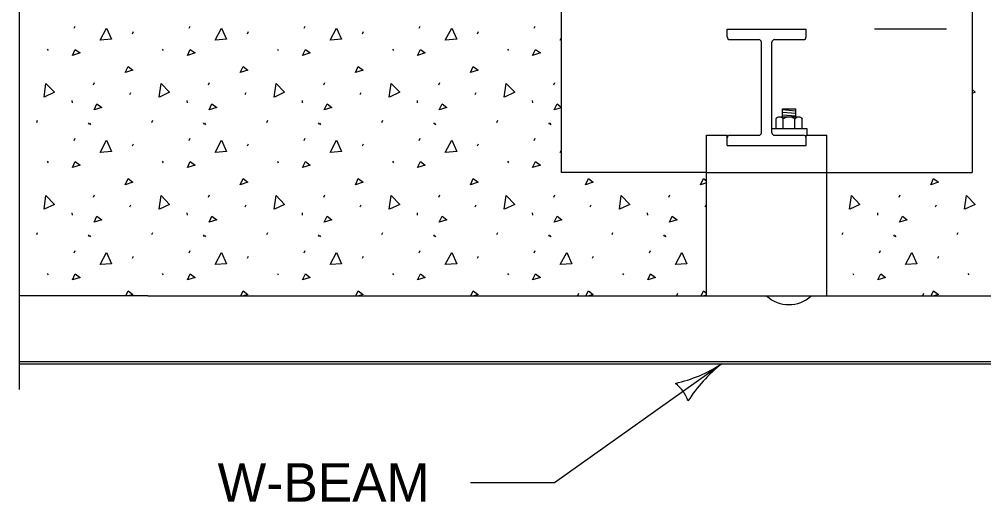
# Model space of a CAD drawing. Extents: x 49991.4 to 50021, y 49987.6 to 50011.4.
# Drawn here: x 50005.327 to 50006.829, y 49990.485 to 49991.236 of the extents above; entities that cross this region are included whole.
import ezdxf

# ---------------------------------------------------------------- set-up
doc = ezdxf.new("R2010")
doc.units = 0
for name, color, linetype in [('Level 1', 7, 'Continuous'), ('Level 2', 7, 'Continuous'), ('Level 3', 7, 'Continuous'), ('Level 4', 7, 'Continuous'), ('Level 6', 7, 'Continuous')]:
    doc.layers.add(name, color=color, linetype=linetype)

msp = doc.modelspace()

# ---------------------------------------------------------------- linework, layer by layer
at = {"layer": 'Level 1'}
for p, q in [((50006.1711, 49991.3177), (50006.1711, 49990.9977)), ((50006.8111, 49991.3177), (50006.8111, 49990.9977)), ((50005.4125, 49991.2224), (50005.414, 49991.2257)), ((50005.5917, 49991.2224), (50005.5932, 49991.2257)), ((50005.7708, 49991.2224), (50005.7723, 49991.2257)), ((50005.95, 49991.2224), (50005.9515, 49991.2257)), ((50006.1291, 49991.2224), (50006.1306, 49991.2257)), ((50005.5033, 49991.2138), (50005.5048, 49991.2171)), ((50005.6824, 49991.2138), (50005.6839, 49991.2171)), ((50005.8616, 49991.2138), (50005.8631, 49991.2171)), ((50006.0407, 49991.2138), (50006.0422, 49991.2171)), ((50006.4294, 49991.2209), (50006.5524, 49991.2209)), ((50006.4294, 49991.2088), (50006.4294, 49991.2209)), ((50006.5524, 49991.2088), (50006.5524, 49991.2209)), ((50006.1696, 49991.2037), (50006.1711, 49991.2067)), ((50006.1711, 49991.2038), (50006.1699, 49991.2037)), ((50006.4335, 49991.2047), (50006.4786, 49991.2047)), ((50006.4827, 49991.0598), (50006.4827, 49991.2007)), ((50006.4991, 49991.0598), (50006.4991, 49991.2007)), ((50006.5032, 49991.2047), (50006.5483, 49991.2047)), ((50005.3707, 49991.1899), (50005.3722, 49991.1877)), ((50005.4099, 49991.1802), (50005.4144, 49991.1895)), ((50005.4218, 49991.184), (50005.4099, 49991.1802)), ((50005.4144, 49991.1895), (50005.4218, 49991.184)), ((50005.5499, 49991.1899), (50005.5514, 49991.1877)), ((50005.5891, 49991.1802), (50005.5935, 49991.1895)), ((50005.601, 49991.184), (50005.5891, 49991.1802)), ((50005.5935, 49991.1895), (50005.601, 49991.184)), ((50005.7291, 49991.1899), (50005.7305, 49991.1877)), ((50005.7682, 49991.1802), (50005.7727, 49991.1895)), ((50005.7801, 49991.184), (50005.7682, 49991.1802)), ((50005.7727, 49991.1895), (50005.7801, 49991.184)), ((50005.9082, 49991.1899), (50005.9097, 49991.1877)), ((50005.9474, 49991.1802), (50005.9518, 49991.1895)), ((50005.9593, 49991.184), (50005.9474, 49991.1802)), ((50005.9518, 49991.1895), (50005.9593, 49991.184)), ((50006.0874, 49991.1899), (50006.0889, 49991.1877)), ((50006.1265, 49991.1802), (50006.131, 49991.1895)), ((50006.1385, 49991.184), (50006.1265, 49991.1802)), ((50006.131, 49991.1895), (50006.1385, 49991.184)), ((50005.4429, 49991.1343), (50005.4443, 49991.1377)), ((50005.622, 49991.1343), (50005.6235, 49991.1377)), ((50005.8012, 49991.1343), (50005.8027, 49991.1377)), ((50005.9803, 49991.1343), (50005.9818, 49991.1377)), ((50006.1595, 49991.1343), (50006.161, 49991.1377)), ((50005.4995, 49991.1191), (50005.501, 49991.1224)), ((50005.6787, 49991.1191), (50005.6802, 49991.1224)), ((50005.8579, 49991.1191), (50005.8594, 49991.1224)), ((50006.037, 49991.1191), (50006.0385, 49991.1224)), ((50005.4091, 49991.1097), (50005.4094, 49991.1063)), ((50005.5882, 49991.1097), (50005.5886, 49991.1063)), ((50005.7674, 49991.1097), (50005.7677, 49991.1063)), ((50005.9465, 49991.1097), (50005.9469, 49991.1063)), ((50006.1257, 49991.1097), (50006.1261, 49991.1063)), ((50006.1711, 49991.0986), (50006.1602, 49991.0952)), ((50006.5154, 49991.0969), (50006.5364, 49991.0969)), ((50006.5154, 49991.084), (50006.5154, 49991.0969)), ((50006.5154, 49991.0957), (50006.5364, 49991.0939)), ((50006.5154, 49991.0918), (50006.5364, 49991.0902)), ((50006.5364, 49991.0841), (50006.5364, 49991.0969)), ((50005.3543, 49991.0758), (50005.3558, 49991.0792)), ((50005.4345, 49991.0753), (50005.436, 49991.0731)), ((50005.4365, 49991.0744), (50005.438, 49991.0722)), ((50005.5335, 49991.0758), (50005.535, 49991.0792)), ((50005.6137, 49991.0753), (50005.6152, 49991.0731)), ((50005.6157, 49991.0744), (50005.6172, 49991.0722)), ((50005.7126, 49991.0758), (50005.7141, 49991.0792)), ((50005.7928, 49991.0753), (50005.7943, 49991.0731)), ((50005.7948, 49991.0744), (50005.7963, 49991.0722)), ((50005.8918, 49991.0758), (50005.8933, 49991.0792)), ((50005.972, 49991.0753), (50005.9735, 49991.0731)), ((50005.974, 49991.0744), (50005.9755, 49991.0722)), ((50006.071, 49991.0758), (50006.0724, 49991.0792)), ((50006.1511, 49991.0753), (50006.1526, 49991.0731)), ((50006.1531, 49991.0744), (50006.1546, 49991.0722)), ((50006.5052, 49991.0812), (50006.5052, 49991.0661)), ((50006.5407, 49991.0841), (50006.511, 49991.084)), ((50006.5154, 49991.0878), (50006.5364, 49991.0861)), ((50006.5166, 49991.0661), (50006.5166, 49991.0812)), ((50006.535, 49991.0661), (50006.535, 49991.0811)), ((50006.5464, 49991.0661), (50006.5464, 49991.0812)), ((50006.4991, 49991.0661), (50006.5536, 49991.0661)), ((50006.5536, 49991.0661), (50006.5536, 49991.0558)), ((50005.4125, 49991.0476), (50005.414, 49991.051)), ((50005.5917, 49991.0476), (50005.5932, 49991.051)), ((50005.7708, 49991.0476), (50005.7723, 49991.051)), ((50005.95, 49991.0476), (50005.9515, 49991.051)), ((50006.1291, 49991.0476), (50006.1306, 49991.051)), ((50006.397, 49991.0558), (50006.4294, 49991.0558)), ((50006.397, 49990.8057), (50006.397, 49991.0558)), ((50006.4294, 49991.0397), (50006.4294, 49991.0558)), ((50006.4335, 49991.0558), (50006.4786, 49991.0558)), ((50006.5032, 49991.0558), (50006.5483, 49991.0558)), ((50006.5524, 49991.0397), (50006.5524, 49991.0558)), ((50006.5524, 49991.0558), (50006.5846, 49991.0558)), ((50006.5846, 49990.8057), (50006.5846, 49991.0558)), ((50005.5033, 49991.0391), (50005.5048, 49991.0424)), ((50005.6824, 49991.0391), (50005.6839, 49991.0424)), ((50005.8616, 49991.0391), (50005.8631, 49991.0424)), ((50006.0407, 49991.0391), (50006.0422, 49991.0424)), ((50006.1696, 49991.029), (50006.1711, 49991.0319)), ((50006.1711, 49991.0291), (50006.1699, 49991.029)), ((50006.4294, 49991.0397), (50006.5524, 49991.0397)), ((50005.3707, 49991.0152), (50005.3722, 49991.013)), ((50005.4099, 49991.0055), (50005.4144, 49991.0148)), ((50005.4144, 49991.0148), (50005.4218, 49991.0092)), ((50005.5499, 49991.0152), (50005.5514, 49991.013)), ((50005.5891, 49991.0055), (50005.5935, 49991.0148)), ((50005.5935, 49991.0148), (50005.601, 49991.0092)), ((50005.7291, 49991.0152), (50005.7305, 49991.013)), ((50005.7682, 49991.0055), (50005.7727, 49991.0148)), ((50005.7727, 49991.0148), (50005.7801, 49991.0092)), ((50005.9082, 49991.0152), (50005.9097, 49991.013)), ((50005.9474, 49991.0055), (50005.9518, 49991.0148)), ((50005.9518, 49991.0148), (50005.9593, 49991.0092)), ((50006.0874, 49991.0152), (50006.0889, 49991.013)), ((50006.1265, 49991.0055), (50006.131, 49991.0148)), ((50006.131, 49991.0148), (50006.1385, 49991.0092)), ((50005.4218, 49991.0092), (50005.4099, 49991.0055)), ((50005.601, 49991.0092), (50005.5891, 49991.0055)), ((50005.7801, 49991.0092), (50005.7682, 49991.0055)), ((50005.9593, 49991.0092), (50005.9474, 49991.0055)), ((50006.1385, 49991.0092), (50006.1265, 49991.0055)), ((50006.3971, 49990.9977), (50006.1711, 49990.9977)), ((50006.5846, 49990.9977), (50006.8111, 49990.9977)), ((50006.3971, 49990.9817), (50006.3879, 49990.9788)), ((50005.4429, 49990.9596), (50005.4443, 49990.963)), ((50005.622, 49990.9596), (50005.6235, 49990.963)), ((50005.8012, 49990.9596), (50005.8027, 49990.963)), ((50005.9803, 49990.9596), (50005.9818, 49990.963)), ((50006.1595, 49990.9596), (50006.161, 49990.963)), ((50006.3386, 49990.9596), (50006.3401, 49990.963)), ((50006.697, 49990.9596), (50006.6985, 49990.963)), ((50005.4995, 49990.9443), (50005.501, 49990.9477)), ((50005.6787, 49990.9443), (50005.6802, 49990.9477)), ((50005.8579, 49990.9443), (50005.8594, 49990.9477)), ((50006.037, 49990.9443), (50006.0385, 49990.9477)), ((50006.2162, 49990.9443), (50006.2177, 49990.9477)), ((50006.3953, 49990.9443), (50006.3968, 49990.9477)), ((50006.7537, 49990.9443), (50006.7551, 49990.9477)), ((50005.4091, 49990.935), (50005.4094, 49990.9316)), ((50005.5882, 49990.935), (50005.5886, 49990.9316)), ((50005.7674, 49990.935), (50005.7677, 49990.9316)), ((50005.9465, 49990.935), (50005.9469, 49990.9316)), ((50006.1257, 49990.935), (50006.1261, 49990.9316)), ((50006.3048, 49990.935), (50006.3052, 49990.9316)), ((50006.6632, 49990.935), (50006.6635, 49990.9316)), ((50005.3543, 49990.9011), (50005.3558, 49990.9044)), ((50005.4345, 49990.9006), (50005.436, 49990.8983)), ((50005.4365, 49990.8997), (50005.438, 49990.8975)), ((50005.5335, 49990.9011), (50005.535, 49990.9044)), ((50005.6137, 49990.9006), (50005.6152, 49990.8983)), ((50005.6157, 49990.8997), (50005.6172, 49990.8975)), ((50005.7126, 49990.9011), (50005.7141, 49990.9044)), ((50005.7928, 49990.9006), (50005.7943, 49990.8983)), ((50005.7948, 49990.8997), (50005.7963, 49990.8975)), ((50005.8918, 49990.9011), (50005.8933, 49990.9044)), ((50005.972, 49990.9006), (50005.9735, 49990.8983)), ((50005.974, 49990.8997), (50005.9755, 49990.8975)), ((50006.071, 49990.9011), (50006.0724, 49990.9044)), ((50006.1511, 49990.9006), (50006.1526, 49990.8983)), ((50006.1531, 49990.8997), (50006.1546, 49990.8975)), ((50006.2501, 49990.9011), (50006.2516, 49990.9044)), ((50006.3303, 49990.9006), (50006.3318, 49990.8983)), ((50006.3323, 49990.8997), (50006.3338, 49990.8975)), ((50006.6084, 49990.9011), (50006.6099, 49990.9044)), ((50006.6886, 49990.9006), (50006.6901, 49990.8983)), ((50006.6906, 49990.8997), (50006.6921, 49990.8975)), ((50006.7876, 49990.9011), (50006.7891, 49990.9044)), ((50005.4125, 49990.8729), (50005.414, 49990.8763)), ((50005.5033, 49990.8643), (50005.5048, 49990.8677)), ((50005.5917, 49990.8729), (50005.5932, 49990.8763)), ((50005.6824, 49990.8643), (50005.6839, 49990.8677)), ((50005.7708, 49990.8729), (50005.7723, 49990.8763)), ((50005.8616, 49990.8643), (50005.8631, 49990.8677)), ((50005.95, 49990.8729), (50005.9515, 49990.8763)), ((50006.0407, 49990.8643), (50006.0422, 49990.8677)), ((50006.1291, 49990.8729), (50006.1306, 49990.8763)), ((50006.2199, 49990.8643), (50006.2214, 49990.8677)), ((50006.3083, 49990.8729), (50006.3098, 49990.8763)), ((50006.6666, 49990.8729), (50006.6681, 49990.8763)), ((50006.7574, 49990.8643), (50006.7589, 49990.8677)), ((50005.3707, 49990.8405), (50005.3722, 49990.8382)), ((50005.4099, 49990.8308), (50005.4144, 49990.8401)), ((50005.4218, 49990.8345), (50005.4099, 49990.8308)), ((50005.4144, 49990.8401), (50005.4218, 49990.8345)), ((50005.5499, 49990.8405), (50005.5514, 49990.8382)), ((50005.5891, 49990.8308), (50005.5935, 49990.8401)), ((50005.601, 49990.8345), (50005.5891, 49990.8308)), ((50005.5935, 49990.8401), (50005.601, 49990.8345)), ((50005.7291, 49990.8405), (50005.7305, 49990.8382)), ((50005.7682, 49990.8308), (50005.7727, 49990.8401)), ((50005.7801, 49990.8345), (50005.7682, 49990.8308)), ((50005.7727, 49990.8401), (50005.7801, 49990.8345)), ((50005.9082, 49990.8405), (50005.9097, 49990.8382)), ((50005.9474, 49990.8308), (50005.9518, 49990.8401)), ((50005.9593, 49990.8345), (50005.9474, 49990.8308)), ((50005.9518, 49990.8401), (50005.9593, 49990.8345)), ((50006.0874, 49990.8405), (50006.0889, 49990.8382)), ((50006.1265, 49990.8308), (50006.131, 49990.8401)), ((50006.1385, 49990.8345), (50006.1265, 49990.8308)), ((50006.131, 49990.8401), (50006.1385, 49990.8345)), ((50006.2665, 49990.8405), (50006.268, 49990.8382)), ((50006.3057, 49990.8308), (50006.3102, 49990.8401)), ((50006.3176, 49990.8345), (50006.3057, 49990.8308)), ((50006.3102, 49990.8401), (50006.3176, 49990.8345)), ((50006.6248, 49990.8405), (50006.6263, 49990.8382)), ((50006.664, 49990.8308), (50006.6685, 49990.8401)), ((50006.6759, 49990.8345), (50006.664, 49990.8308)), ((50006.6685, 49990.8401), (50006.6759, 49990.8345)), ((50006.804, 49990.8405), (50006.8055, 49990.8382)), ((50005.5272, 49990.8057), (50005.3272, 49990.8057)), ((50005.5272, 49990.8057), (50007.455, 49990.8057)), ((50006.1968, 49990.8063), (50006.1983, 49990.8097)), ((50006.3509, 49990.8063), (50006.3524, 49990.8097)), ((50006.3971, 49990.807), (50006.393, 49990.8057)), ((50006.7343, 49990.8063), (50006.7358, 49990.8097)), ((50005.3272, 49990.7036), (50007.655, 49990.7036)), ((50005.3272, 49990.6997), (50007.655, 49990.6997))]:
    msp.add_line(p, q, dxfattribs=at)
for points in [[(50005.4529, 49991.2037), (50005.463, 49991.2227), (50005.4708, 49991.2052), (50005.4533, 49991.2037)], [(50005.6321, 49991.2037), (50005.6421, 49991.2227), (50005.65, 49991.2052), (50005.6325, 49991.2037)], [(50005.8112, 49991.2037), (50005.8213, 49991.2227), (50005.8291, 49991.2052), (50005.8116, 49991.2037)], [(50005.9904, 49991.2037), (50006.0005, 49991.2227), (50006.0083, 49991.2052), (50005.9908, 49991.2037)], [(50005.4922, 49991.1536), (50005.4966, 49991.1629), (50005.5041, 49991.1573), (50005.4922, 49991.1536)], [(50005.6713, 49991.1536), (50005.6758, 49991.1629), (50005.6833, 49991.1573), (50005.6713, 49991.1536)], [(50005.8505, 49991.1536), (50005.8549, 49991.1629), (50005.8624, 49991.1573), (50005.8505, 49991.1536)], [(50006.0296, 49991.1536), (50006.0341, 49991.1629), (50006.0416, 49991.1573), (50006.0296, 49991.1536)], [(50005.3658, 49991.1152), (50005.3687, 49991.1365), (50005.3821, 49991.1227), (50005.3661, 49991.1153)], [(50005.5449, 49991.1152), (50005.5479, 49991.1365), (50005.5612, 49991.1227), (50005.5453, 49991.1153)], [(50005.7241, 49991.1152), (50005.727, 49991.1365), (50005.7404, 49991.1227), (50005.7244, 49991.1153)], [(50005.9032, 49991.1152), (50005.9062, 49991.1365), (50005.9195, 49991.1227), (50005.9036, 49991.1153)], [(50006.0824, 49991.1152), (50006.0853, 49991.1365), (50006.0987, 49991.1227), (50006.0827, 49991.1153)], [(50006.8111, 49991.1271), (50006.8153, 49991.1227), (50006.8111, 49991.1208)], [(50005.4436, 49991.0952), (50005.4481, 49991.1045), (50005.4555, 49991.0989), (50005.4436, 49991.0952)], [(50005.6228, 49991.0952), (50005.6272, 49991.1045), (50005.6347, 49991.0989), (50005.6228, 49991.0952)], [(50005.8019, 49991.0952), (50005.8064, 49991.1045), (50005.8138, 49991.0989), (50005.8019, 49991.0952)], [(50005.9811, 49991.0952), (50005.9855, 49991.1045), (50005.993, 49991.0989), (50005.9811, 49991.0952)], [(50006.1602, 49991.0952), (50006.1647, 49991.1045), (50006.1711, 49991.0997)], [(50005.4529, 49991.029), (50005.463, 49991.048), (50005.4708, 49991.0305), (50005.4533, 49991.029)], [(50005.6321, 49991.029), (50005.6421, 49991.048), (50005.65, 49991.0305), (50005.6325, 49991.029)], [(50005.8112, 49991.029), (50005.8213, 49991.048), (50005.8291, 49991.0305), (50005.8116, 49991.029)], [(50005.9904, 49991.029), (50006.0005, 49991.048), (50006.0083, 49991.0305), (50005.9908, 49991.029)], [(50005.4922, 49990.9788), (50005.4966, 49990.9882), (50005.5041, 49990.9826), (50005.4922, 49990.9788)], [(50005.6713, 49990.9788), (50005.6758, 49990.9882), (50005.6833, 49990.9826), (50005.6713, 49990.9788)], [(50005.8505, 49990.9788), (50005.8549, 49990.9882), (50005.8624, 49990.9826), (50005.8505, 49990.9788)], [(50006.0296, 49990.9788), (50006.0341, 49990.9882), (50006.0416, 49990.9826), (50006.0296, 49990.9788)], [(50006.2088, 49990.9788), (50006.2133, 49990.9882), (50006.2207, 49990.9826), (50006.2088, 49990.9788)], [(50006.3879, 49990.9788), (50006.3924, 49990.9882), (50006.3971, 49990.9847)], [(50006.7463, 49990.9788), (50006.7507, 49990.9882), (50006.7582, 49990.9826), (50006.7463, 49990.9788)], [(50005.3658, 49990.9405), (50005.3687, 49990.9618), (50005.3821, 49990.948), (50005.3661, 49990.9406)], [(50005.5449, 49990.9405), (50005.5479, 49990.9618), (50005.5612, 49990.948), (50005.5453, 49990.9406)], [(50005.7241, 49990.9405), (50005.727, 49990.9618), (50005.7404, 49990.948), (50005.7244, 49990.9406)], [(50005.9032, 49990.9405), (50005.9062, 49990.9618), (50005.9195, 49990.948), (50005.9036, 49990.9406)], [(50006.0824, 49990.9405), (50006.0853, 49990.9618), (50006.0987, 49990.948), (50006.0827, 49990.9406)], [(50006.2616, 49990.9405), (50006.2645, 49990.9618), (50006.2779, 49990.948), (50006.2619, 49990.9406)], [(50006.6199, 49990.9405), (50006.6228, 49990.9618), (50006.6362, 49990.948), (50006.6202, 49990.9406)], [(50006.799, 49990.9405), (50006.802, 49990.9618), (50006.8153, 49990.948), (50006.7994, 49990.9406)], [(50005.4436, 49990.9205), (50005.4481, 49990.9298), (50005.4555, 49990.9242), (50005.4436, 49990.9205)], [(50005.6228, 49990.9205), (50005.6272, 49990.9298), (50005.6347, 49990.9242), (50005.6228, 49990.9205)], [(50005.8019, 49990.9205), (50005.8064, 49990.9298), (50005.8138, 49990.9242), (50005.8019, 49990.9205)], [(50005.9811, 49990.9205), (50005.9855, 49990.9298), (50005.993, 49990.9242), (50005.9811, 49990.9205)], [(50006.1602, 49990.9205), (50006.1647, 49990.9298), (50006.1722, 49990.9242), (50006.1602, 49990.9205)], [(50006.3394, 49990.9205), (50006.3439, 49990.9298), (50006.3513, 49990.9242), (50006.3394, 49990.9205)], [(50006.6977, 49990.9205), (50006.7022, 49990.9298), (50006.7096, 49990.9242), (50006.6977, 49990.9205)], [(50005.4529, 49990.8543), (50005.463, 49990.8733), (50005.4708, 49990.8558), (50005.4533, 49990.8543)], [(50005.6321, 49990.8543), (50005.6421, 49990.8733), (50005.65, 49990.8558), (50005.6325, 49990.8543)], [(50005.8112, 49990.8543), (50005.8213, 49990.8733), (50005.8291, 49990.8558), (50005.8116, 49990.8543)], [(50005.9904, 49990.8543), (50006.0005, 49990.8733), (50006.0083, 49990.8558), (50005.9908, 49990.8543)], [(50006.1696, 49990.8543), (50006.1796, 49990.8733), (50006.1875, 49990.8558), (50006.1699, 49990.8543)], [(50006.3487, 49990.8543), (50006.3588, 49990.8733), (50006.3666, 49990.8558), (50006.3491, 49990.8543)], [(50006.707, 49990.8543), (50006.7171, 49990.8733), (50006.7249, 49990.8558), (50006.7074, 49990.8543)], [(50005.4929, 49990.8057), (50005.4966, 49990.8134), (50005.5041, 49990.8079), (50005.4972, 49990.8057)], [(50005.6721, 49990.8057), (50005.6758, 49990.8134), (50005.6833, 49990.8079), (50005.6763, 49990.8057)], [(50005.8512, 49990.8057), (50005.8549, 49990.8134), (50005.8624, 49990.8079), (50005.8555, 49990.8057)], [(50006.0304, 49990.8057), (50006.0341, 49990.8134), (50006.0416, 49990.8079), (50006.0347, 49990.8057)], [(50006.2095, 49990.8057), (50006.2133, 49990.8134), (50006.2207, 49990.8079), (50006.2138, 49990.8057)], [(50006.3887, 49990.8057), (50006.3924, 49990.8134), (50006.3971, 49990.81)], [(50006.747, 49990.8057), (50006.7507, 49990.8134), (50006.7582, 49990.8079), (50006.7513, 49990.8057)]]:
    msp.add_lwpolyline(points, dxfattribs=at)
for centre, major_axis, start_param, end_param in [((50006.4335, 49991.2088), (0.0041, 0), 3.141593, 4.712389), ((50006.5483, 49991.2088), (0.0041, 0), 4.712389, 6.283185), ((50006.4786, 49991.2007), (0.0041, 0), 0, 1.570796), ((50006.5032, 49991.2007), (-0.0041, 0), 4.712389, 6.283185), ((50006.5109, 49991.077), (0.00714, 0), 0.651429, 2.497647), ((50006.5257, 49991.0686), (-0.0158, 0), 4.078615, 5.329167), ((50006.5408, 49991.0773), (-0.00692, 0), 3.760637, 5.689405), ((50006.4786, 49991.0598), (0.0041, 0), 4.712389, 6.283185), ((50006.5032, 49991.0598), (0.0041, 0), 3.141593, 4.712389), ((50006.4335, 49991.0518), (-0.0041, 0), 4.712389, 6.234181), ((50006.5483, 49991.0518), (-0.0041, 0), 3.190597, 4.712389)]:
    msp.add_ellipse(centre, major_axis=major_axis, ratio=0.983731, start_param=start_param, end_param=end_param, dxfattribs=at)
at = {"layer": 'Level 3'}
for p, q in [((50006.7711, 49991.2209), (50006.659, 49991.2209)), ((50006.1603, 49990.5152), (50006.4207, 49990.6997)), ((50006.0298, 49990.5152), (50006.1603, 49990.5152))]:
    msp.add_line(p, q, dxfattribs=at)
for centre, radius, start, end in [((50006.2998, 49990.8863), 0.2223, 282.7682, 302.9517), ((50006.5646, 49990.5165), 0.233, 128.1395, 147.3894), ((50006.3161, 49990.6256), 0.0548, 17.451, 53.1734)]:
    msp.add_arc(centre, radius, start, end, dxfattribs=at)
at = {"layer": 'Level 4'}
msp.add_line((50006.397, 49990.9977), (50006.5846, 49990.9977), dxfattribs=at)
msp.add_ellipse((50006.5256, 49990.8416), major_axis=(0.0504, 0), ratio=0.983731, start_param=3.951149, end_param=5.473629, dxfattribs=at)
at = {"layer": 'Level 6'}
for p, q in [((50005.3272, 49991.3198), (50005.3272, 49991.2019)), ((50005.3272, 49991.2019), (50005.3272, 49990.6597))]:
    msp.add_line(p, q, dxfattribs=at)

# ---------------------------------------------------------------- texts
at = {"layer": 'Level 2'}
msp.add_text('W-BEAM', height=0.06, dxfattribs=at).set_placement((50005.636, 49990.4852))

doc.saveas('drawing.dxf')
